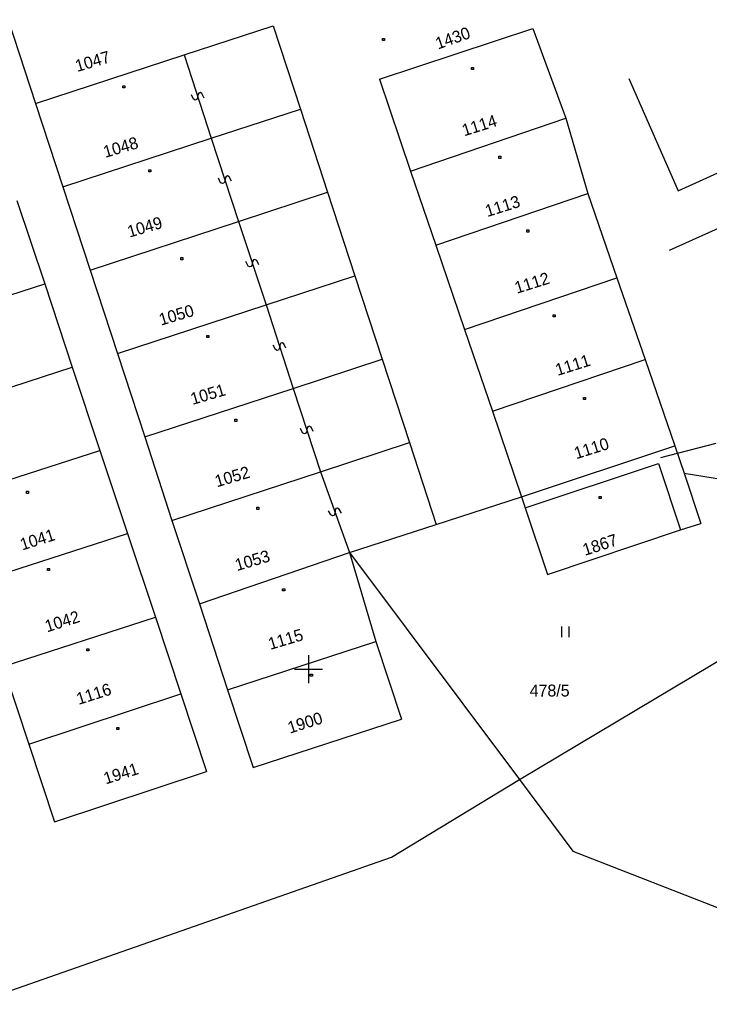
# Model space of a CAD drawing. Extents: x -493352 to -492964, y -1127001 to -1126712.
# Drawn here: x -493212.33 to -493182.87, y -1126754.75 to -1126712.25 of the extents above; entities that cross this region are included whole.
import ezdxf

# ---------------------------------------------------------------- set-up
doc = ezdxf.new("R2010")
doc.units = 0
doc.layers.add('katastrální mapa', color=7, linetype='Continuous')
doc.layers.add('síť', color=7, linetype='Continuous')

msp = doc.modelspace()

# ---------------------------------------------------------------- linework, layer by layer
at = {"layer": 'katastrální mapa'}
for p, q in [((-493212.83, -1126712.25), (-493211.66, -1126715.82)), ((-493205.31, -1126713.74), (-493201.51, -1126712.5)), ((-493201.51, -1126712.5), (-493200.34, -1126716.06)), ((-493196.96, -1126714.78), (-493190.4, -1126712.62)), ((-493190.4, -1126712.62), (-493188.99, -1126716.45)), ((-493190.4, -1126712.62), (-493188.99, -1126716.45)), ((-493196.83, -1126713.04), (-493196.74, -1126713.04)), ((-493196.83, -1126713.13), (-493196.83, -1126713.04)), ((-493196.74, -1126713.13), (-493196.83, -1126713.13)), ((-493196.74, -1126713.04), (-493196.74, -1126713.13)), ((-493211.66, -1126715.82), (-493205.31, -1126713.74)), ((-493205.31, -1126713.74), (-493204.15, -1126717.3)), ((-493193.03, -1126714.28), (-493192.94, -1126714.28)), ((-493193.03, -1126714.37), (-493193.03, -1126714.28)), ((-493192.94, -1126714.37), (-493193.03, -1126714.37)), ((-493192.94, -1126714.28), (-493192.94, -1126714.37)), ((-493196.96, -1126714.78), (-493195.63, -1126718.71)), ((-493186.3, -1126714.76), (-493184.19, -1126719.56)), ((-493184.19, -1126719.56), (-493173.32, -1126714.61)), ((-493207.93, -1126715.07), (-493207.84, -1126715.07)), ((-493207.93, -1126715.16), (-493207.93, -1126715.07)), ((-493207.84, -1126715.16), (-493207.93, -1126715.16)), ((-493207.84, -1126715.07), (-493207.84, -1126715.16)), ((-493204.68, -1126715.38), (-493204.72, -1126715.45)), ((-493204.62, -1126715.36), (-493204.68, -1126715.38)), ((-493204.55, -1126715.4), (-493204.62, -1126715.36)), ((-493204.46, -1126715.59), (-493204.55, -1126715.4)), ((-493211.66, -1126715.82), (-493210.49, -1126719.38)), ((-493204.91, -1126715.64), (-493205, -1126715.45)), ((-493204.84, -1126715.68), (-493204.91, -1126715.64)), ((-493204.78, -1126715.66), (-493204.84, -1126715.68)), ((-493204.74, -1126715.59), (-493204.78, -1126715.66)), ((-493204.72, -1126715.45), (-493204.74, -1126715.59)), ((-493204.15, -1126717.3), (-493200.34, -1126716.06)), ((-493200.34, -1126716.06), (-493199.18, -1126719.62)), ((-493195.63, -1126718.71), (-493188.99, -1126716.45)), ((-493188.99, -1126716.45), (-493188.06, -1126719.67)), ((-493188.99, -1126716.45), (-493188.06, -1126719.67)), ((-493210.49, -1126719.38), (-493204.15, -1126717.3)), ((-493204.15, -1126717.3), (-493202.98, -1126720.87)), ((-493184.56, -1126722.09), (-493173.86, -1126717.29)), ((-493191.86, -1126718.08), (-493191.77, -1126718.08)), ((-493191.86, -1126718.17), (-493191.86, -1126718.08)), ((-493191.77, -1126718.17), (-493191.86, -1126718.17)), ((-493191.77, -1126718.08), (-493191.77, -1126718.17)), ((-493206.82, -1126718.66), (-493206.73, -1126718.66)), ((-493206.82, -1126718.75), (-493206.82, -1126718.66)), ((-493206.73, -1126718.75), (-493206.82, -1126718.75)), ((-493206.73, -1126718.66), (-493206.73, -1126718.75)), ((-493195.63, -1126718.71), (-493194.55, -1126721.88)), ((-493203.75, -1126719.21), (-493203.84, -1126719.02)), ((-493203.67, -1126719.25), (-493203.75, -1126719.21)), ((-493203.57, -1126719.15), (-493203.61, -1126719.23)), ((-493203.56, -1126719.02), (-493203.57, -1126719.15)), ((-493203.52, -1126718.94), (-493203.56, -1126719.02)), ((-493203.46, -1126718.92), (-493203.52, -1126718.94)), ((-493203.38, -1126718.96), (-493203.46, -1126718.92)), ((-493203.29, -1126719.15), (-493203.38, -1126718.96)), ((-493210.49, -1126719.38), (-493209.33, -1126722.95)), ((-493203.61, -1126719.23), (-493203.67, -1126719.25)), ((-493202.98, -1126720.87), (-493199.18, -1126719.62)), ((-493199.18, -1126719.62), (-493198.01, -1126723.19)), ((-493212.46, -1126719.97), (-493211.27, -1126723.53)), ((-493194.55, -1126721.88), (-493188.06, -1126719.67)), ((-493188.06, -1126719.67), (-493186.81, -1126723.27)), ((-493188.06, -1126719.67), (-493186.81, -1126723.27)), ((-493209.33, -1126722.95), (-493202.98, -1126720.87)), ((-493202.98, -1126720.87), (-493201.81, -1126724.43)), ((-493190.66, -1126721.23), (-493190.57, -1126721.23)), ((-493190.66, -1126721.32), (-493190.66, -1126721.23)), ((-493190.57, -1126721.32), (-493190.66, -1126721.32)), ((-493190.57, -1126721.23), (-493190.57, -1126721.32)), ((-493194.55, -1126721.88), (-493193.32, -1126725.48)), ((-493205.45, -1126722.41), (-493205.36, -1126722.41)), ((-493205.45, -1126722.5), (-493205.45, -1126722.41)), ((-493205.36, -1126722.5), (-493205.45, -1126722.5)), ((-493205.36, -1126722.41), (-493205.36, -1126722.5)), ((-493202.58, -1126722.77), (-493202.67, -1126722.58)), ((-493202.39, -1126722.58), (-493202.4, -1126722.72)), ((-493202.35, -1126722.51), (-493202.39, -1126722.58)), ((-493202.29, -1126722.49), (-493202.35, -1126722.51)), ((-493202.21, -1126722.53), (-493202.29, -1126722.49)), ((-493202.12, -1126722.72), (-493202.21, -1126722.53)), ((-493209.33, -1126722.95), (-493208.16, -1126726.51)), ((-493202.5, -1126722.81), (-493202.58, -1126722.77)), ((-493202.44, -1126722.79), (-493202.5, -1126722.81)), ((-493202.4, -1126722.72), (-493202.44, -1126722.79)), ((-493201.81, -1126724.43), (-493198.01, -1126723.19)), ((-493198.01, -1126723.19), (-493196.85, -1126726.75)), ((-493193.32, -1126725.48), (-493186.81, -1126723.27)), ((-493186.81, -1126723.27), (-493185.6, -1126726.76)), ((-493186.81, -1126723.27), (-493185.6, -1126726.76)), ((-493217.79, -1126725.64), (-493211.27, -1126723.53)), ((-493211.27, -1126723.53), (-493210.09, -1126727.09)), ((-493208.16, -1126726.51), (-493201.81, -1126724.43)), ((-493201.81, -1126724.43), (-493200.65, -1126728)), ((-493189.54, -1126724.85), (-493189.45, -1126724.85)), ((-493189.54, -1126724.94), (-493189.54, -1126724.85)), ((-493189.45, -1126724.94), (-493189.54, -1126724.94)), ((-493189.45, -1126724.85), (-493189.45, -1126724.94)), ((-493193.32, -1126725.48), (-493192.13, -1126728.98)), ((-493204.34, -1126725.74), (-493204.25, -1126725.74)), ((-493204.34, -1126725.83), (-493204.34, -1126725.74)), ((-493204.25, -1126725.83), (-493204.34, -1126725.83)), ((-493204.25, -1126725.74), (-493204.25, -1126725.83)), ((-493201.41, -1126726.34), (-493201.5, -1126726.15)), ((-493201.34, -1126726.38), (-493201.41, -1126726.34)), ((-493201.28, -1126726.36), (-493201.34, -1126726.38)), ((-493201.24, -1126726.28), (-493201.28, -1126726.36)), ((-493201.22, -1126726.15), (-493201.24, -1126726.28)), ((-493201.18, -1126726.07), (-493201.22, -1126726.15)), ((-493201.12, -1126726.05), (-493201.18, -1126726.07)), ((-493201.05, -1126726.09), (-493201.12, -1126726.05)), ((-493200.96, -1126726.28), (-493201.05, -1126726.09)), ((-493208.16, -1126726.51), (-493206.99, -1126730.07)), ((-493200.65, -1126728), (-493196.85, -1126726.75)), ((-493196.85, -1126726.75), (-493195.68, -1126730.32)), ((-493192.13, -1126728.98), (-493185.6, -1126726.76)), ((-493185.6, -1126726.76), (-493184.33, -1126730.45)), ((-493185.6, -1126726.76), (-493184.33, -1126730.45)), ((-493216.61, -1126729.2), (-493210.09, -1126727.09)), ((-493210.09, -1126727.09), (-493208.91, -1126730.65)), ((-493206.99, -1126730.07), (-493200.65, -1126728)), ((-493200.65, -1126728), (-493199.48, -1126731.56)), ((-493188.24, -1126728.39), (-493188.15, -1126728.39)), ((-493188.24, -1126728.48), (-493188.24, -1126728.39)), ((-493188.15, -1126728.48), (-493188.24, -1126728.48)), ((-493188.15, -1126728.39), (-493188.15, -1126728.48)), ((-493192.13, -1126728.98), (-493190.89, -1126732.64)), ((-493203.15, -1126729.32), (-493203.06, -1126729.32)), ((-493203.15, -1126729.41), (-493203.15, -1126729.32)), ((-493203.06, -1126729.41), (-493203.15, -1126729.41)), ((-493203.06, -1126729.32), (-493203.06, -1126729.41)), ((-493200.25, -1126729.9), (-493200.34, -1126729.71)), ((-493200.07, -1126729.85), (-493200.11, -1126729.92)), ((-493200.06, -1126729.71), (-493200.07, -1126729.85)), ((-493200.02, -1126729.64), (-493200.06, -1126729.71)), ((-493199.96, -1126729.62), (-493200.02, -1126729.64)), ((-493199.88, -1126729.66), (-493199.96, -1126729.62)), ((-493199.79, -1126729.85), (-493199.88, -1126729.66)), ((-493206.99, -1126730.07), (-493205.83, -1126733.64)), ((-493200.17, -1126729.94), (-493200.25, -1126729.9)), ((-493200.11, -1126729.92), (-493200.17, -1126729.94)), ((-493215.43, -1126732.76), (-493208.91, -1126730.65)), ((-493208.91, -1126730.65), (-493207.73, -1126734.2)), ((-493199.48, -1126731.56), (-493195.68, -1126730.32)), ((-493195.68, -1126730.32), (-493194.54, -1126733.82)), ((-493190.89, -1126732.64), (-493184.33, -1126730.45)), ((-493190.89, -1126732.64), (-493184.33, -1126730.45)), ((-493184.94, -1126730.96), (-493182.57, -1126730.34)), ((-493184.33, -1126730.45), (-493183.93, -1126731.63)), ((-493190.73, -1126733.11), (-493185.04, -1126731.21)), ((-493185.04, -1126731.21), (-493184.1, -1126734.05)), ((-493205.83, -1126733.64), (-493199.48, -1126731.56)), ((-493199.48, -1126731.56), (-493198.24, -1126735.01)), ((-493183.93, -1126731.63), (-493183.22, -1126733.77)), ((-493183.93, -1126731.63), (-493179.19, -1126732.39)), ((-493212.05, -1126732.4), (-493211.96, -1126732.4)), ((-493212.05, -1126732.49), (-493212.05, -1126732.4)), ((-493211.96, -1126732.4), (-493211.96, -1126732.49)), ((-493211.96, -1126732.49), (-493212.05, -1126732.49)), ((-493194.54, -1126733.82), (-493190.89, -1126732.64)), ((-493194.54, -1126733.82), (-493190.89, -1126732.64)), ((-493190.89, -1126732.64), (-493190.73, -1126733.11)), ((-493187.57, -1126732.62), (-493187.48, -1126732.62)), ((-493187.57, -1126732.71), (-493187.57, -1126732.62)), ((-493187.48, -1126732.71), (-493187.57, -1126732.71)), ((-493187.48, -1126732.62), (-493187.48, -1126732.71)), ((-493202.21, -1126733.08), (-493202.12, -1126733.08)), ((-493202.21, -1126733.17), (-493202.21, -1126733.08)), ((-493202.12, -1126733.17), (-493202.21, -1126733.17)), ((-493202.12, -1126733.08), (-493202.12, -1126733.17)), ((-493199.04, -1126733.41), (-493199.14, -1126733.23)), ((-493198.85, -1126733.22), (-493198.87, -1126733.35)), ((-493198.82, -1126733.14), (-493198.85, -1126733.22)), ((-493198.76, -1126733.12), (-493198.82, -1126733.14)), ((-493198.68, -1126733.16), (-493198.76, -1126733.12)), ((-493198.58, -1126733.34), (-493198.68, -1126733.16)), ((-493190.73, -1126733.11), (-493189.78, -1126735.96)), ((-493205.83, -1126733.64), (-493204.66, -1126737.21)), ((-493198.96, -1126733.45), (-493199.04, -1126733.41)), ((-493198.9, -1126733.43), (-493198.96, -1126733.45)), ((-493198.87, -1126733.35), (-493198.9, -1126733.43)), ((-493198.24, -1126735.01), (-493194.54, -1126733.82)), ((-493198.24, -1126735.01), (-493194.54, -1126733.82)), ((-493189.78, -1126735.96), (-493184.1, -1126734.05)), ((-493184.1, -1126734.05), (-493183.22, -1126733.77)), ((-493214.24, -1126736.31), (-493207.73, -1126734.2)), ((-493207.73, -1126734.2), (-493206.54, -1126737.78)), ((-493204.66, -1126737.21), (-493198.24, -1126735.01)), ((-493198.24, -1126735.01), (-493197.11, -1126738.82)), ((-493198.24, -1126735.01), (-493190.98, -1126744.72)), ((-493198.24, -1126735.01), (-493190.98, -1126744.72)), ((-493211.15, -1126735.7), (-493211.06, -1126735.7)), ((-493211.15, -1126735.79), (-493211.15, -1126735.7)), ((-493211.06, -1126735.79), (-493211.15, -1126735.79)), ((-493211.06, -1126735.7), (-493211.06, -1126735.79)), ((-493190.98, -1126744.72), (-493176.67, -1126736.17)), ((-493201.1, -1126736.57), (-493201.01, -1126736.57)), ((-493201.1, -1126736.66), (-493201.1, -1126736.57)), ((-493201.01, -1126736.57), (-493201.01, -1126736.66)), ((-493201.01, -1126736.66), (-493201.1, -1126736.66)), ((-493204.66, -1126737.21), (-493203.45, -1126740.89)), ((-493213.05, -1126739.89), (-493206.54, -1126737.78)), ((-493206.54, -1126737.78), (-493205.45, -1126741.05)), ((-493189.16, -1126738.63), (-493189.16, -1126738.18)), ((-493188.86, -1126738.18), (-493188.86, -1126738.63)), ((-493209.47, -1126739.13), (-493209.38, -1126739.13)), ((-493209.47, -1126739.22), (-493209.47, -1126739.13)), ((-493209.38, -1126739.13), (-493209.38, -1126739.22)), ((-493203.45, -1126740.89), (-493197.11, -1126738.82)), ((-493197.11, -1126738.82), (-493196.02, -1126742.14)), ((-493209.38, -1126739.22), (-493209.47, -1126739.22)), ((-493213.05, -1126739.89), (-493211.95, -1126743.21)), ((-493199.92, -1126740.21), (-493199.83, -1126740.21)), ((-493199.92, -1126740.3), (-493199.92, -1126740.21)), ((-493199.83, -1126740.3), (-493199.92, -1126740.3)), ((-493199.83, -1126740.21), (-493199.83, -1126740.3)), ((-493203.45, -1126740.89), (-493202.36, -1126744.21)), ((-493211.95, -1126743.21), (-493205.45, -1126741.05)), ((-493205.45, -1126741.05), (-493204.35, -1126744.37)), ((-493202.36, -1126744.21), (-493196.02, -1126742.14)), ((-493208.19, -1126742.49), (-493208.1, -1126742.49)), ((-493208.19, -1126742.58), (-493208.19, -1126742.49)), ((-493208.1, -1126742.58), (-493208.19, -1126742.58)), ((-493208.1, -1126742.49), (-493208.1, -1126742.58)), ((-493211.95, -1126743.21), (-493210.85, -1126746.53)), ((-493210.85, -1126746.53), (-493204.35, -1126744.37)), ((-493196.45, -1126748.04), (-493190.98, -1126744.72)), ((-493190.98, -1126744.72), (-493188.69, -1126747.78)), ((-493190.98, -1126744.72), (-493188.69, -1126747.78)), ((-493228.16, -1126759.15), (-493196.45, -1126748.04)), ((-493188.69, -1126747.78), (-493175.4, -1126752.97)), ((-493188.69, -1126747.78), (-493175.4, -1126752.97))]:
    msp.add_line(p, q, dxfattribs=at)
at = {"layer": 'síť'}
for p, q in [((-493200, -1126739.4), (-493200, -1126740.6)), ((-493200.6, -1126740), (-493199.4, -1126740))]:
    msp.add_line(p, q, dxfattribs=at)

# ---------------------------------------------------------------- texts
at = {"layer": 'katastrální mapa'}
for s, rotation, p in [('1430', 19.539, (-493194.46, -1126713.52)), ('1047', 16.443, (-493209.88, -1126714.48)), ('1114', 17.415, (-493193.34, -1126717.23)), ('1048', 16.443, (-493208.68, -1126718.15)), ('1113', 17.415, (-493192.35, -1126720.68)), ('1049', 16.443, (-493207.65, -1126721.56)), ('1112', 17.415, (-493191.09, -1126723.96)), ('1050', 16.443, (-493206.3, -1126725.32)), ('1111', 17.415, (-493189.35, -1126727.47)), ('1051', 16.443, (-493204.95, -1126728.71)), ('1110', 17.415, (-493188.55, -1126731.03)), ('1052', 16.443, (-493203.91, -1126732.23)), ('1041', 17.532, (-493212.23, -1126734.93)), ('1867', 17.991, (-493188.18, -1126735.16)), ('1053', 16.443, (-493203.05, -1126735.81)), ('1042', 17.532, (-493211.17, -1126738.43)), ('1115', 16.443, (-493201.63, -1126739.18)), ('1116', 17.532, (-493209.82, -1126741.53)), ('1900', 17.532, (-493200.79, -1126742.76)), ('1941', 17.532, (-493208.66, -1126744.93))]:
    msp.add_text(s, height=0.51, rotation=rotation, dxfattribs=at).set_placement(p)
for s, height, p in [('478/10', 0.03, (-493184.94, -1126730.96)), ('478/5', 0.51, (-493190.54, -1126741.17))]:
    msp.add_text(s, height=height, dxfattribs=at).set_placement(p)

doc.saveas('drawing.dxf')
